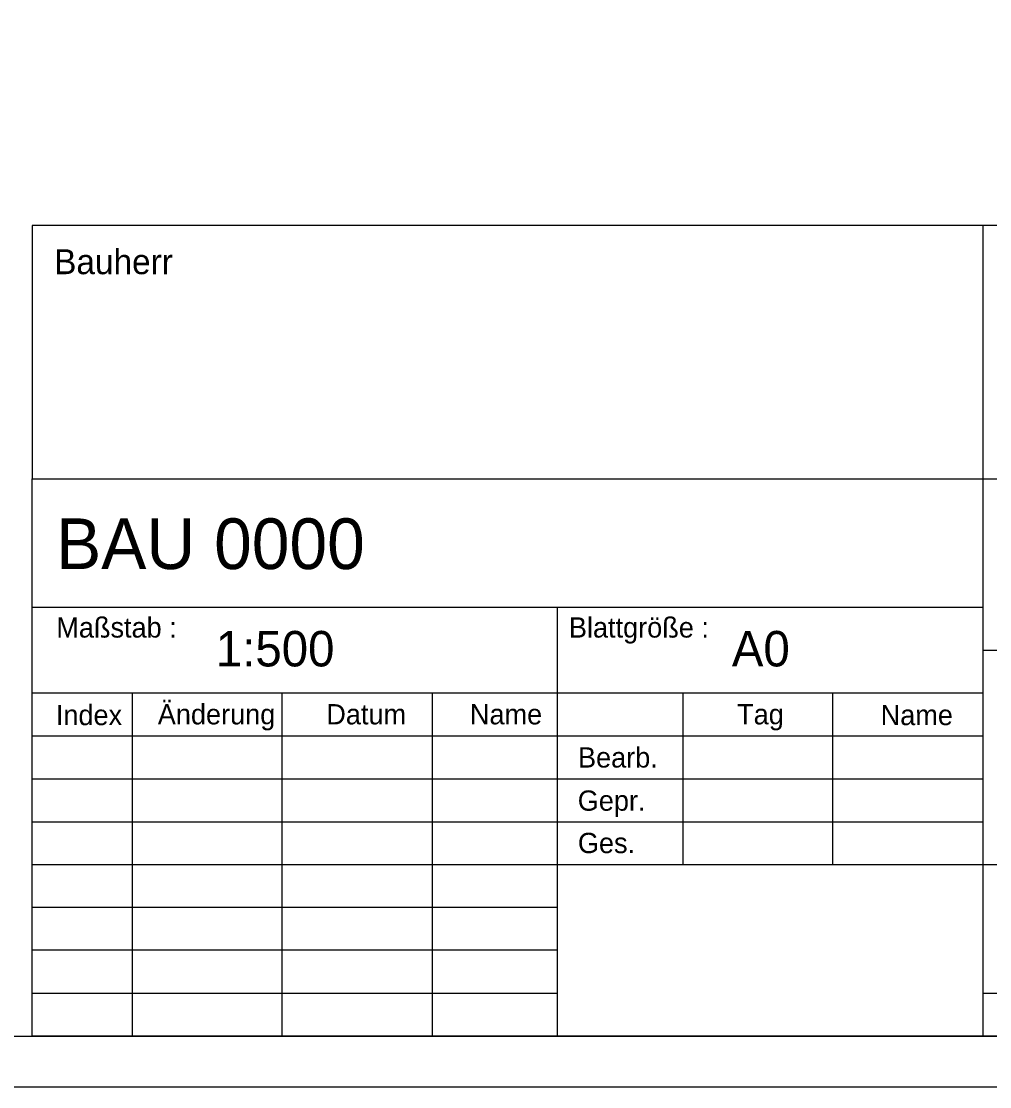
# Model space of a CAD drawing. Extents: x 0 to 594, y 0 to 420.
# Drawn here: x 502.5 to 550.3, y 0 to 52.6 of the extents above; entities that cross this region are included whole.
import ezdxf

# ---------------------------------------------------------------- set-up
doc = ezdxf.new("R2010")
doc.units = 0
doc.layers.add('90_Plankopf', color=7, linetype='Continuous')

msp = doc.modelspace()

# ---------------------------------------------------------------- linework, layer by layer
at = {"layer": '90_Plankopf'}
for p, q in [((592, 42.495), (503.06, 42.495)), ((503.06, 42.495), (503.06, 29.995)), ((550, 29.995), (550, 42.495)), ((503.06, 29.995), (592, 29.995)), ((503.06, 2.5), (503.06, 29.995)), ((503.06, 29.995), (592, 29.995)), ((550, 2.5), (550, 29.995)), ((503.06, 23.65), (550, 23.65)), ((529.001, 2.5), (529.001, 23.65)), ((550, 21.535), (592, 21.535)), ((503.06, 19.435), (550, 19.435)), ((508.001, 19.42), (508.001, 2.5)), ((515.413, 2.5), (515.413, 19.42)), ((522.825, 2.5), (522.825, 19.42)), ((535.177, 19.42), (535.177, 10.96)), ((542.589, 10.96), (542.589, 19.42)), ((503.06, 17.315), (550, 17.315)), ((503.06, 15.19), (550, 15.19)), ((503.06, 13.075), (550, 13.075)), ((503.06, 10.96), (550, 10.96)), ((503.06, 10.96), (550, 10.96)), ((529.001, 10.96), (550, 10.96)), ((550, 10.96), (592, 10.96)), ((529.001, 8.845), (503.06, 8.845)), ((529.001, 6.73), (503.06, 6.73)), ((503.06, 4.615), (529.001, 4.615)), ((550, 4.615), (592, 4.615)), ((592, 2.5), (503.06, 2.5)), ((503.06, 2.5), (529.001, 2.5)), ((508.9, 2.5), (592, 2.5)), ((508.9, 2.5), (592, 2.5))]:
    msp.add_line(p, q, dxfattribs=at)
for points in [[(0, 0), (594.5, 0), (594.5, 420.5), (0, 420.5)], [(12.5, 2.5), (592, 2.5), (592, 418), (12.5, 418)]]:
    msp.add_lwpolyline(points, close=True, dxfattribs=at)

# ---------------------------------------------------------------- texts
for s, height, p in [('Bauherr', 1.2318, (504.151, 40.087)), ('BAU 0000      ', 2.5, (504.245, 25.538)), ('Maßstab :', 1, (504.258, 22.158)), ('Blattgröße :', 0.99995, (529.558, 22.158)), ('1:500    ', 1.75, (512.131, 20.734)), ('A0       ', 1.75, (537.6, 20.734)), ('Änderung', 1, (509.267, 17.875)), ('Index', 1, (504.235, 17.837)), ('Datum', 1, (517.584, 17.875)), ('Name', 1, (524.673, 17.875)), ('Tag', 1, (537.861, 17.875)), ('Name', 1, (544.946, 17.837)), ('Bearb.', 1, (530.007, 15.745)), ('Gepr.', 1, (529.995, 13.615)), ('Ges.', 1, (530.002, 11.524))]:
    msp.add_text(s, height=height, dxfattribs=at).set_placement(p)

doc.saveas('drawing.dxf')
